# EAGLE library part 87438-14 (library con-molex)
Wire-to-Board 1.50mm (.059") Pitch Header - Right Angle, SMT, Shrouded Source: http://www.molex.com/product/micro/87438.html
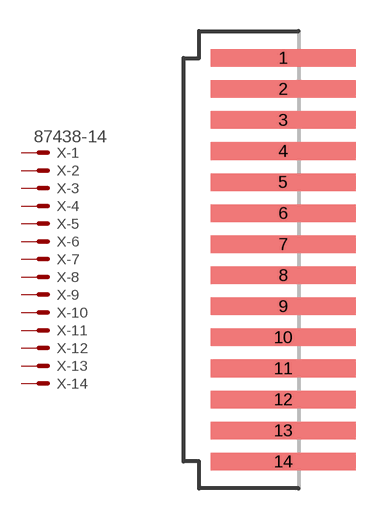
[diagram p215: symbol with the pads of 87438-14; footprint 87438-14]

Designator prefix X; gates -1=MV -2=M -3=M -4=M -5=M -6=M -7=M -8=M -9=M -10=M -11=M -12=M -13=M -14=M

## 87438-14 (MPN: 87438-1443; OC_FARNELL: unknown; OC_NEWARK: 94M1107)  [87438-14]
1  -1:S  pas
2  -2:S  pas
3  -3:S  pas
4  -4:S  pas
5  -5:S  pas
6  -6:S  pas
7  -7:S  pas
8  -8:S  pas
9  -9:S  pas
10  -10:S  pas
11  -11:S  pas
12  -12:S  pas
13  -13:S  pas
14  -14:S  pas

## Footprint 87438-14 (pad centres in mm)
Wire-to-Board 1.50mm (.059") Pitch Header - Right Angle, SMT, Shrouded Source: http://www.molex.com/product/micro/87438.html
smd 7 x 0.85: 1 0,9.75; 2 0,8.25; 3 0,6.75; 4 0,5.25; 5 0,3.75; 6 0,2.25; 7 0,0.75; 8 0,-0.75; 9 0,-2.25; 10 0,-3.75; 11 0,-5.25; 12 0,-6.75; 13 0,-8.25; 14 0,-9.75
